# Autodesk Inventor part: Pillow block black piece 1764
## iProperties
Created: 2009-01
Part Number: Pillow block black piece 1764
Document SubType Name: Modeling
Designer: lwoods
Density: 1.4 g/cm^3
Material: PVC-Piping
Mass: 16.083 g
Surface Area: 61.8162 cm^2
Volume: 11.4879 cm^3
Author: lwoods
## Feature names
1. Extrusion2
2. Revolution1
3. Extrusion3
4. Extrusion4
5. Fillet4
6. Fillet5
7. Extrusion5
8. Fillet6
9. Fillet7
10. Revolution2
